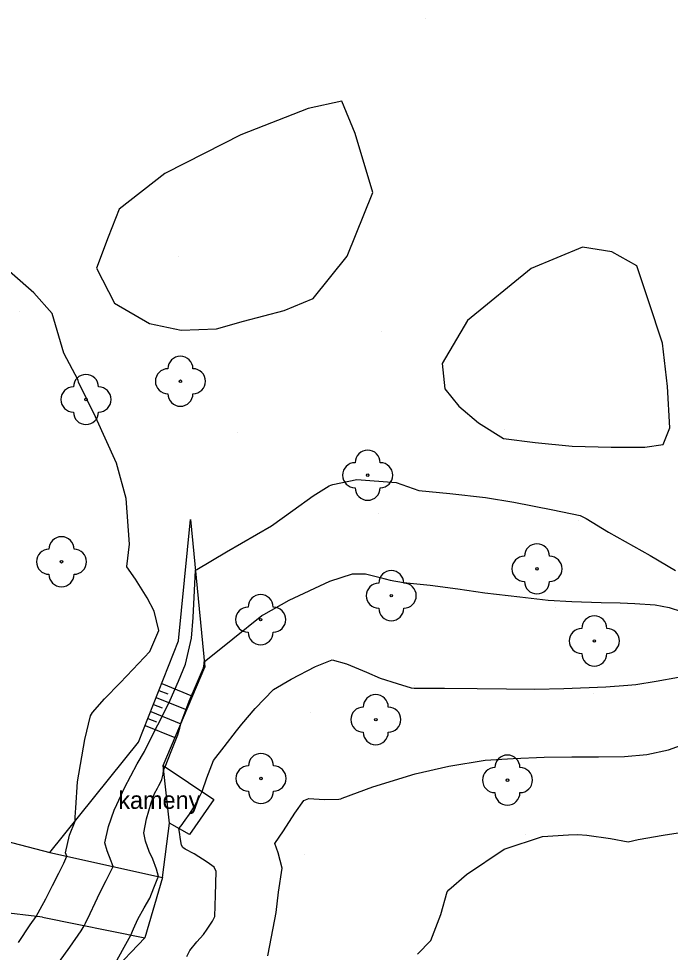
# Model space of a CAD drawing. Extents: x -448957 to -448612, y -1107690 to -1107245.
# Drawn here: x -448740.89 to -448714.86, y -1107383.27 to -1107346.01 of the extents above; entities that cross this region are included whole.
import ezdxf

# ---------------------------------------------------------------- set-up
doc = ezdxf.new("R2010")
doc.units = 0
for name, color, linetype in [('22', 7, 'Continuous'), ('Default', 7, 'Continuous'), ('Vrstva 1', 7, 'Continuous'), ('Vrstva 10', 7, 'Continuous'), ('Vrstva 11', 7, 'Continuous'), ('Vrstva 14', 7, 'Continuous'), ('Vrstva 15', 7, 'Continuous'), ('Vrstva 16', 7, 'Continuous'), ('Vrstva 17', 7, 'Continuous'), ('Vrstva 22', 7, 'Continuous'), ('Vrstva 42', 7, 'Continuous')]:
    doc.layers.add(name, color=color, linetype=linetype)

# ---------------------------------------------------------------- blocks, each defined once
blk = doc.blocks.new('STROM$5')
at = {"layer": '22'}
blk.add_circle((0, 0), 0.5, dxfattribs=at)
for centre, start, end in [((0, 5), 0, 180), ((-5, 0), 90, 270), ((5, 0), 270, 90), ((0, -5), 180, 0)]:
    blk.add_arc(centre, 5, start, end, dxfattribs=at)
blk = doc.blocks.new('POINT_DISPLAY')
at = {"layer": 'Default'}
blk.add_line((0, 0), (0, 0), dxfattribs=at)

msp = doc.modelspace()

# ---------------------------------------------------------------- linework, layer by layer
at = {"layer": 'Vrstva 10'}
for p, q in [((-448734.873, -1107378.116), (-448735.125, -1107375.818)), ((-448735.125, -1107375.818), (-448733.095, -1107377.166)), ((-448733.095, -1107377.166), (-448734.074, -1107378.57)), ((-448734.074, -1107378.57), (-448734.873, -1107378.116))]:
    msp.add_line(p, q, dxfattribs=at)
at = {"layer": 'Vrstva 11'}
for p, q in [((-448745.046, -1107377.875), (-448739.644, -1107379.291)), ((-448739.644, -1107379.291), (-448735.151, -1107380.283)), ((-448735.151, -1107380.283), (-448735.861, -1107382.696)), ((-448739.939, -1107381.871), (-448744.774, -1107381.304)), ((-448739.939, -1107381.871), (-448735.861, -1107382.696))]:
    msp.add_line(p, q, dxfattribs=at)
at = {"layer": 'Vrstva 14'}
for p, q in [((-448734.507, -1107370.833), (-448734.024, -1107365.998)), ((-448734.024, -1107365.998), (-448733.459, -1107371.891)), ((-448736.105, -1107374.879), (-448734.507, -1107370.833)), ((-448735.125, -1107375.818), (-448733.459, -1107371.891)), ((-448739.644, -1107379.291), (-448736.105, -1107374.879)), ((-448735.151, -1107380.283), (-448734.873, -1107378.116)), ((-448735.861, -1107382.696), (-448739.463, -1107386.469))]:
    msp.add_line(p, q, dxfattribs=at)
at = {"layer": 'Vrstva 15'}
for p, q in [((-448735.29, -1107372.817), (-448734.942, -1107372.959)), ((-448735.18, -1107372.538), (-448733.947, -1107373.042)), ((-448735.401, -1107373.096), (-448734.182, -1107373.595)), ((-448735.511, -1107373.375), (-448735.167, -1107373.516)), ((-448735.731, -1107373.933), (-448735.391, -1107374.072)), ((-448735.621, -1107373.654), (-448734.416, -1107374.147)), ((-448735.841, -1107374.212), (-448734.651, -1107374.7))]:
    msp.add_line(p, q, dxfattribs=at)
at = {"layer": 'Vrstva 16'}
msp.add_lwpolyline([(-448739.433, -1107383.881), (-448738.852, -1107383.068), (-448738.402, -1107382.409), (-448738.272, -1107382.208), (-448738.224, -1107382.11), (-448738.041, -1107381.721), (-448737.841, -1107381.292), (-448737.648, -1107380.898), (-448737.395, -1107380.401), (-448737.193, -1107380.004), (-448737.114, -1107379.85), (-448737.202, -1107379.63), (-448737.356, -1107379.225), (-448737.452, -1107378.899), (-448737.304, -1107378.251), (-448737.075, -1107377.604), (-448736.978, -1107377.37), (-448736.664, -1107376.702), (-448736.158, -1107375.746), (-448735.873, -1107375.254), (-448735.651, -1107374.814), (-448735.333, -1107374.198), (-448735.153, -1107373.839), (-448734.847, -1107373.205), (-448734.505, -1107372.446), (-448734.236, -1107371.774), (-448733.991, -1107370.727), (-448733.927, -1107369.904), (-448733.872, -1107368.837), (-448733.83, -1107368.016), (-448733.783, -1107367.988), (-448732.594, -1107367.287), (-448730.791, -1107366.243), (-448729.943, -1107365.642), (-448729.136, -1107365.046), (-448728.488, -1107364.659), (-448728.43, -1107364.626), (-448728.342, -1107364.605), (-448727.386, -1107364.398), (-448725.815, -1107364.518), (-448724.905, -1107364.842), (-448723.672, -1107364.954), (-448722.24, -1107365.119), (-448721.11, -1107365.3), (-448719.555, -1107365.615), (-448718.467, -1107365.843), (-448718.226, -1107365.958), (-448717.33, -1107366.497), (-448715.663, -1107367.438), (-448714.656, -1107368.027)], dxfattribs=at)
at = {"layer": 'Vrstva 17'}
for points in [[(-448737.07, -1107357.358), (-448735.669, -1107358.179), (-448734.406, -1107358.434), (-448732.997, -1107358.388), (-448731.913, -1107358.082), (-448730.29, -1107357.653), (-448729.125, -1107357.172), (-448727.774, -1107355.483), (-448726.747, -1107352.945), (-448727.456, -1107350.594), (-448727.981, -1107349.299), (-448729.325, -1107349.594), (-448732.02, -1107350.643), (-448733.459, -1107351.376), (-448735.062, -1107352.191), (-448736.886, -1107353.614), (-448737.325, -1107354.725), (-448737.79, -1107355.968), (-448737.07, -1107357.358)], [(-448721.529, -1107362.758), (-448720.257, -1107362.921), (-448718.788, -1107363.067), (-448717.226, -1107363.106), (-448715.878, -1107363.104), (-448715.152, -1107363.006), (-448714.885, -1107362.342), (-448714.973, -1107360.69), (-448715.178, -1107358.96), (-448715.741, -1107357.273), (-448716.198, -1107355.876), (-448717.204, -1107355.314), (-448718.368, -1107355.122), (-448720.428, -1107355.978), (-448722.972, -1107358.06), (-448723.972, -1107359.764), (-448723.868, -1107360.779), (-448723.318, -1107361.476), (-448722.527, -1107362.144), (-448721.529, -1107362.758)], [(-448740.9, -1107382.883), (-448740.441, -1107382.18), (-448740.19, -1107381.842), (-448740.029, -1107381.544), (-448739.812, -1107381.138), (-448739.541, -1107380.605), (-448739.285, -1107380.107), (-448739.094, -1107379.708), (-448738.971, -1107379.44), (-448739.027, -1107379.296), (-448738.861, -1107378.596), (-448738.639, -1107378.039), (-448738.634, -1107377.882), (-448738.616, -1107377.505), (-448738.54, -1107376.47), (-448738.255, -1107374.777), (-448738.02, -1107373.834), (-448737.949, -1107373.706), (-448737.468, -1107373.158), (-448736.846, -1107372.516), (-448736.337, -1107371.984), (-448735.652, -1107371.263), (-448735.3, -1107370.431), (-448735.478, -1107369.654), (-448735.767, -1107369.122), (-448736.233, -1107368.382), (-448736.568, -1107367.883), (-448736.569, -1107367.879), (-448736.569, -1107367.875), (-448736.471, -1107366.984), (-448736.605, -1107365.158), (-448736.991, -1107363.742), (-448737.822, -1107361.903), (-448738.503, -1107360.517), (-448738.518, -1107360.434), (-448739.093, -1107359.361), (-448739.559, -1107357.778), (-448740.294, -1107356.95), (-448742.039, -1107355.433)], [(-448737.124, -1107383.86), (-448736.744, -1107383.187), (-448736.41, -1107382.585), (-448736.303, -1107382.333), (-448736.13, -1107381.942), (-448735.876, -1107381.495), (-448735.655, -1107381.114), (-448735.489, -1107380.696), (-448735.331, -1107380.3), (-448735.305, -1107380.249), (-448735.394, -1107379.957), (-448735.531, -1107379.556), (-448735.683, -1107379.244), (-448735.827, -1107378.84), (-448735.889, -1107378.506), (-448735.791, -1107377.945), (-448735.607, -1107377.309), (-448735.464, -1107376.936), (-448735.355, -1107376.714), (-448735.291, -1107376.611), (-448735.228, -1107376.498), (-448735.173, -1107376.369), (-448735.126, -1107376.156), (-448735.105, -1107376.004), (-448735.043, -1107375.872), (-448734.802, -1107375.261), (-448734.543, -1107374.594), (-448734.461, -1107374.32), (-448734.397, -1107374.102), (-448734.261, -1107373.713), (-448734.087, -1107373.245), (-448733.788, -1107372.565), (-448733.506, -1107371.914), (-448733.483, -1107371.773), (-448733.479, -1107371.683), (-448732.342, -1107370.765), (-448731.176, -1107369.83), (-448731.098, -1107369.787), (-448730.087, -1107369.213), (-448728.46, -1107368.455), (-448727.555, -1107368.166), (-448727.038, -1107368.16), (-448726.459, -1107368.308), (-448726.057, -1107368.422), (-448725.524, -1107368.509), (-448724.456, -1107368.613), (-448723.349, -1107368.758), (-448722.269, -1107368.923), (-448720.878, -1107369.086), (-448719.745, -1107369.219), (-448718.799, -1107369.274), (-448717.623, -1107369.314), (-448716.861, -1107369.329), (-448716.283, -1107369.343), (-448715.475, -1107369.405), (-448714.904, -1107369.515), (-448714.411, -1107369.665)], [(-448734.18, -1107383.437), (-448734.057, -1107383.198), (-448733.774, -1107382.849), (-448733.511, -1107382.558), (-448733.371, -1107382.35), (-448733.156, -1107382.022), (-448733.061, -1107381.844), (-448733.033, -1107380.985), (-448733.007, -1107380.048), (-448733.086, -1107379.879), (-448733.371, -1107379.67), (-448733.89, -1107379.346), (-448734.25, -1107379.149), (-448734.338, -1107379.09), (-448734.394, -1107378.991), (-448734.434, -1107378.766), (-448734.476, -1107378.474), (-448734.49, -1107378.334), (-448734.407, -1107378.225), (-448734.237, -1107377.995), (-448734.069, -1107377.758), (-448733.917, -1107377.511), (-448733.784, -1107377.267), (-448733.643, -1107377.006), (-448733.561, -1107376.856), (-448733.377, -1107376.302), (-448733.106, -1107375.62), (-448732.692, -1107375.068), (-448732.198, -1107374.427), (-448731.986, -1107374.161), (-448731.448, -1107373.539), (-448730.715, -1107372.781), (-448730.015, -1107372.363), (-448729.037, -1107371.861), (-448728.37, -1107371.597), (-448727.795, -1107371.757), (-448727, -1107372.086), (-448726.454, -1107372.331), (-448725.778, -1107372.542), (-448725.221, -1107372.709), (-448725.101, -1107372.724), (-448723.878, -1107372.729), (-448722.581, -1107372.746), (-448721.406, -1107372.759), (-448720.279, -1107372.77), (-448719.121, -1107372.743), (-448717.439, -1107372.678), (-448716.561, -1107372.615), (-448716.243, -1107372.584), (-448715.424, -1107372.455), (-448714.542, -1107372.295)], [(-448730.947, -1107383.409), (-448730.794, -1107382.647), (-448730.605, -1107381.683), (-448730.52, -1107380.869), (-448730.366, -1107379.911), (-448730.523, -1107379.305), (-448730.658, -1107378.928), (-448730.313, -1107378.418), (-448729.865, -1107377.724), (-448729.502, -1107377.211), (-448729.297, -1107377.131), (-448728.688, -1107377.166), (-448728.109, -1107377.161), (-448728.029, -1107377.15), (-448727.978, -1107377.121), (-448726.744, -1107376.673), (-448725.053, -1107376.151), (-448723.712, -1107375.846), (-448722.255, -1107375.602), (-448721.147, -1107375.538), (-448719.903, -1107375.482), (-448718.798, -1107375.47), (-448717.731, -1107375.468), (-448716.7, -1107375.456), (-448715.804, -1107375.37), (-448714.936, -1107375.187), (-448714.083, -1107374.888)], [(-448724.959, -1107383.349), (-448724.428, -1107382.793), (-448724.027, -1107381.76), (-448723.782, -1107380.861), (-448723.711, -1107380.778), (-448723.002, -1107380.169), (-448721.504, -1107379.16), (-448719.976, -1107378.649), (-448718.931, -1107378.576), (-448718.556, -1107378.566), (-448718.203, -1107378.593), (-448717.259, -1107378.73), (-448716.55, -1107378.855), (-448716.146, -1107378.768), (-448715.148, -1107378.59), (-448714.371, -1107378.481)]]:
    msp.add_lwpolyline(points, dxfattribs=at)

# ---------------------------------------------------------------- block references
at = {"layer": 'Vrstva 1', "xscale": 0.1, "yscale": 0.10000000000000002}
for p in [(-448734.024, -1107365.998), (-448734.024, -1107365.998), (-448734.507, -1107370.833), (-448733.459, -1107371.891), (-448733.459, -1107371.891), (-448736.105, -1107374.879), (-448736.105, -1107374.879), (-448735.125, -1107375.818), (-448735.125, -1107375.818), (-448733.095, -1107377.166), (-448733.095, -1107377.166), (-448734.873, -1107378.116), (-448734.873, -1107378.116), (-448734.074, -1107378.57), (-448739.644, -1107379.291), (-448739.644, -1107379.291), (-448739.644, -1107379.291), (-448735.151, -1107380.283), (-448735.151, -1107380.283), (-448735.151, -1107380.283), (-448739.939, -1107381.871), (-448739.939, -1107381.871), (-448735.861, -1107382.696), (-448735.861, -1107382.696)]:
    msp.add_blockref('POINT_DISPLAY', p, dxfattribs=at)
at = {"layer": 'Vrstva 14', "xscale": 0.1, "yscale": 0.10000000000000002}
for p in [(-448724.656, -1107346.008), (-448734.493, -1107355.508), (-448740.842, -1107357.685), (-448726.387, -1107358.49), (-448721.493, -1107362.399), (-448732.167, -1107362.518), (-448726.514, -1107365.755), (-448718.514, -1107366.027), (-448719.464, -1107369.509), (-448725.098, -1107372.636), (-448717.94, -1107372.94), (-448729.245, -1107373.703), (-448720.662, -1107378.553), (-448729.478, -1107379.355)]:
    msp.add_blockref('POINT_DISPLAY', p, dxfattribs=at)
at = {"layer": 'Vrstva 22', "xscale": 0.1, "yscale": 0.10000000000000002}
for p in [(-448734.432, -1107360.479), (-448738.206, -1107361.208), (-448726.953, -1107364.229), (-448739.183, -1107367.683), (-448720.19, -1107367.966), (-448726.01, -1107369.038), (-448731.228, -1107369.994), (-448717.898, -1107370.844), (-448726.629, -1107373.985), (-448731.215, -1107376.334), (-448721.369, -1107376.399)]:
    msp.add_blockref('STROM$5', p, dxfattribs=at)

# ---------------------------------------------------------------- texts
at = {"layer": 'Vrstva 42'}
msp.add_text('kameny', height=0.7, dxfattribs=at).set_placement((-448736.915, -1107377.545))

doc.saveas('drawing.dxf')
